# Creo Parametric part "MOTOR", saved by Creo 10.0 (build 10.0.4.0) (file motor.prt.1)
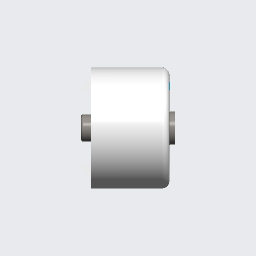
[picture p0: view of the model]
Units: millimeter Kilogram Sec (mmKs); MM, KILOGRAM, SECS

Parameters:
  SCREW_SIZE = "M2.5x.45"
  METRIC = "YES"

Other parameters: PITCH, DRILL_POINT_ANGLE, DRILL_DEPTH, DRILL_DIAMETER, THREAD_DIAMETER, THREADS_PER_INCH, THREAD_DEPTH, THREAD_LENGTH

Created from: XX_SOLID_PART_MMKS_NEW_ABS.PRT

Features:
  1. datum plane "RIGHT"
  2. datum plane "TOP"
  3. datum plane "FRONT"
  4. coordinate system
  5. sketch "Sketch 1"
  6. revolve "Revolve 1"
  7. round "Round 1"
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
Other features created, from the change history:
  extruded cut "Extrude 1"
  extrusion "Extrude 2"
  round "Round 2"
  sketch "Sketch 2"
  extruded cut "Extrude 3"
  extrusion "Extrude 4"
  sketch "Sketch 3"
  hole "Hole 1"
  pattern "Pattern 1"
  hole "Hole 1 [2]"
  hole "Hole 1 [3]"
  hole "Hole 1 [4]"
  hole "Hole 1 [5]"
  hole "Hole 1 [6]"

Notes: M2.5x.45 | 4.920 | 2.05 |  DRILL (  | 2.050 | 6.150 | HOLES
